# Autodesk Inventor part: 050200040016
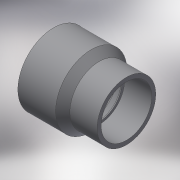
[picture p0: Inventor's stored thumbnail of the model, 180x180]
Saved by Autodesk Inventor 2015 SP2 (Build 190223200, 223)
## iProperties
Created: 2017-10
Part Number: 050200040016
Material: Generic
Description: PLASSON REDUCING SOCKET M.F.40(32)16 CEMENTED
Document SubType Name: Modeling
Designer: KIM
Density: 1 g/cm^3
Appearance: Default
Author: KIM
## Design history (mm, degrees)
derived "050200.ipt"
feature "Solid1::050200.ipt"
tag "TaggingFeature1"
body "Solid1"
other parameters: "d1" = 26, "d2" = 14, "d3" = 22, "d4" = 16, "d5" = 22, "d6" = 32, "d8" = 14.4, "d9" = 45 deg, "d12" = 0.32, "d_" = 32, "d_1" = 16, "L_" = 26, "l_" = 22, "l_1" = 14, "E_" = 22, "d11" = 7.32815
